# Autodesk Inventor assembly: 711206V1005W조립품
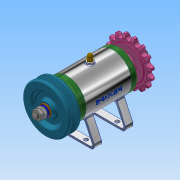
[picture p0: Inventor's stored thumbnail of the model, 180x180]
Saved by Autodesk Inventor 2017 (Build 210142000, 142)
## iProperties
Part Number: 711206V1005W조립품
Material: 일반
Document SubType Name: Assembly
Designer: Administrator
Author: Administrator
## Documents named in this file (16)
- C:\Users\Administrator\Desktop\711206V1005\711206V1005W조립품.iam
- C:\Users\Administrator\Desktop\711206V1005\본체.ipt
- C:\Users\Administrator\Desktop\711206V1005\V벨트풀리.ipt
- C:\Users\Administrator\Desktop\711206V1005\너트 M8.ipt
- C:\Users\Administrator\Desktop\711206V1005\니플 M6 x 0.75.ipt
- C:\Users\Administrator\Desktop\711206V1005\베어링 6002.ipt
- C:\Users\Administrator\Desktop\711206V1005\볼트 M4 x 12.ipt
- C:\Users\Administrator\Desktop\711206V1005\볼트 M6 x 8.ipt
- C:\Users\Administrator\Desktop\711206V1005\스프로킷.ipt
- C:\Users\Administrator\Desktop\711206V1005\스프링와셔 8.ipt
- C:\Users\Administrator\Desktop\711206V1005\오일 실 15 x 25 x 7.ipt
- C:\Users\Administrator\Desktop\711206V1005\와셔 6 x 11.5.ipt
- C:\Users\Administrator\Desktop\711206V1005\와셔 8 x 17.ipt
- C:\Users\Administrator\Desktop\711206V1005\축.ipt
- C:\Users\Administrator\Desktop\711206V1005\커버.ipt
- C:\Users\Administrator\Desktop\711206V1005\키 3 x 3.ipt
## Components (11 placed, 3 different names)
1. V벨트풀리:1
2. KS B 2023 6002 - 15 x 32 x 9:1
3. KS B 2023 6002 - 15 x 32 x 9:2
4. ISO 4762 M4 x 12:2
5. ISO 4762 M4 x 12:3
6. ISO 4762 M4 x 12:4
7. ISO 4762 M4 x 12:5
8. ISO 4762 M4 x 12:1
9. ISO 4762 M4 x 12:6
10. ISO 4762 M4 x 12:7
11. ISO 4762 M4 x 12:8
